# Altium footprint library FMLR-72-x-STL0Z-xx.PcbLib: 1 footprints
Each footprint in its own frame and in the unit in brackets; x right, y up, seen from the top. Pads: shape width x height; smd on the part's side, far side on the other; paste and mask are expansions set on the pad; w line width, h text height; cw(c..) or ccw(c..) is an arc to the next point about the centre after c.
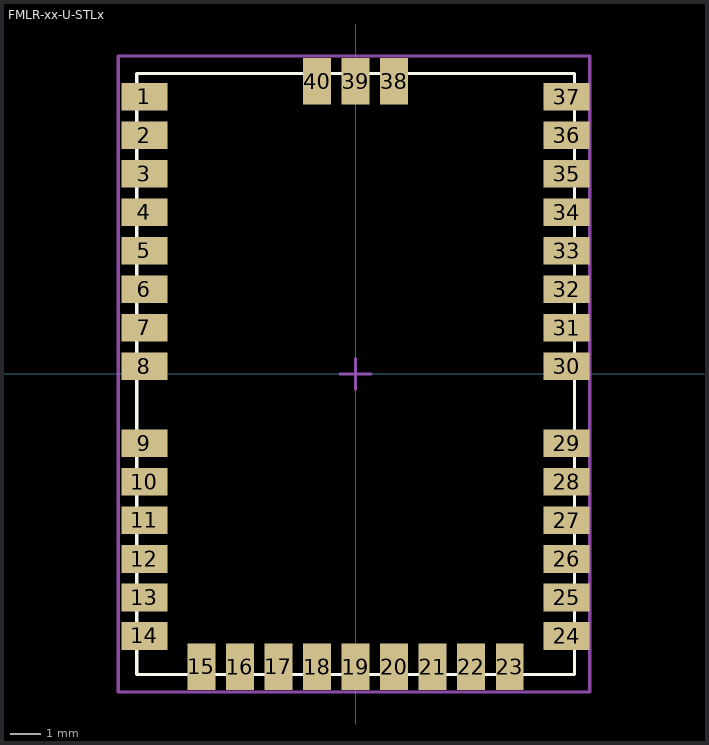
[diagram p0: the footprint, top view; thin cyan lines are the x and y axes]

## FMLR-xx-U-STLx [mm] "LoRa Module with ceramic antenna and STM32L0"
height 0.8
pads (40):
  rect 1.5x0.9 smd: 1(-6.85,9) 2(-6.85,7.75) 3(-6.85,6.5) 4(-6.85,5.25) 5(-6.85,4) 6(-6.85,2.75) 7(-6.85,1.5) 8(-6.85,0.25) 9(-6.85,-2.25) 10(-6.85,-3.5) 11(-6.85,-4.75) 12(-6.85,-6) 13(-6.85,-7.25) 14(-6.85,-8.5) 24(6.85,-8.5) 25(6.85,-7.25) 26(6.85,-6) 27(6.85,-4.75) 28(6.85,-3.5) 29(6.85,-2.25) 30(6.85,0.25) 31(6.85,1.5) 32(6.85,2.75) 33(6.85,4) 34(6.85,5.25) 35(6.85,6.5) 36(6.85,7.75) 37(6.85,9)
  rect 0.9x1.5 smd: 15(-5,-9.5) 16(-3.75,-9.5) 17(-2.5,-9.5) 18(-1.25,-9.5) 19(0,-9.5) 20(1.25,-9.5) 21(2.5,-9.5) 22(3.75,-9.5) 23(5,-9.5) 38(1.25,9.5) 39(0,9.5) 40(-1.25,9.5)
Top Overlay:
  lines w0.1: -7.1,9.745 -7.1,-9.75 7.1,-9.75 7.1,9.745 ; -7.1,9.75 7.1,9.75
Mechanical 15:
  lines w0.1: -0.5,0 0.5,0 ; 0,-0.5 0,0.5 ; -7.7,-10.325 7.6,-10.325 7.6,10.325 -7.7,10.325 -7.7,-10.325
3D body: height 1.26, standoff -1.02, extent -8.975,3.925 -8.975,3.925
3D body: height 1.2, standoff 0, extent -7.1,-9.75 7.1,9.75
